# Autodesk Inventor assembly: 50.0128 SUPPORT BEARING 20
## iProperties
Created: 2007-07
Part Number: 50.0128 SUPPORT BEARING 20
Document SubType Name: Assembly
Designer: Andy Moles
Author: Andy Moles
